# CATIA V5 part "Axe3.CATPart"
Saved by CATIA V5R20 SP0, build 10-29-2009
Part number: Axe3
Bounding box of the stored display mesh (mm): x 15.475 to 22.475, y 32.5 to 39.5, z -18 to -3.5
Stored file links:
  E:\Boulot\SeaTech\2eme ANNEE\FabricationAdditive\TP_MOSM_CREM\Projet Sauterelle de serrage\CAO Assemblage Sauterelle\Axe3.CATPart
  E:\Boulot\SeaTech\2eme ANNEE\FabricationAdditive\TP_MOSM_CREM\Projet Sauterelle de serrage\CAO Assemblage Sauterelle\Sauterelle_horizontale_05120-06.CATPart
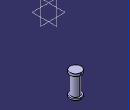
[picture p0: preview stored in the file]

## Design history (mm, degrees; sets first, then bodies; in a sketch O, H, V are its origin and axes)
Body1 (main body)
  Solid1 "05120-06_6": solid without history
